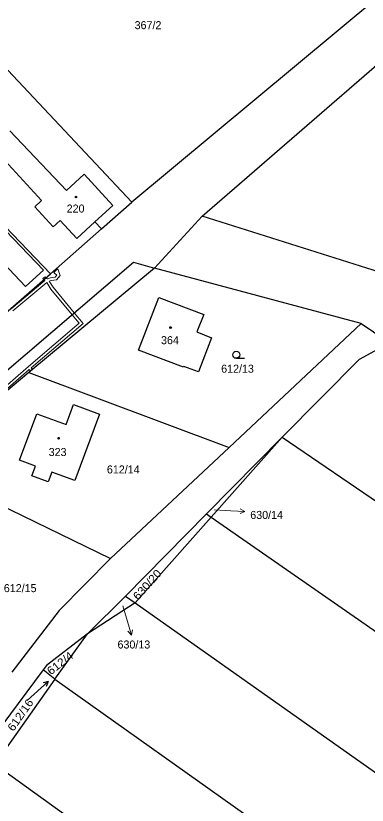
# Model space of a CAD drawing. Extents: x -694609 to -690140, y -1033292 to -1029794.
# Drawn here: x -692178.9 to -692104.2, y -1031453.2 to -1031285.6 of the extents above; entities that cross this region are included whole.
import ezdxf
from ezdxf.enums import TextEntityAlignment as Align

# ---------------------------------------------------------------- set-up
doc = ezdxf.new("R2010")
doc.units = 0
doc.header["$LTSCALE"] = 0.68
for name, color, linetype, lineweight in [('1', 7, 'Continuous', 25), ('13', 7, 'Continuous', 13), ('3', 7, 'Continuous', 25), ('4', 7, 'Continuous', 13), ('5', 7, 'Continuous', 25), ('7', 7, 'Continuous', 13)]:
    doc.layers.add(name, color=color, linetype=linetype, lineweight=lineweight)
doc.layers.add('2', color=7, linetype='Continuous')

msp = doc.modelspace()

# ---------------------------------------------------------------- linework, layer by layer
at = {"layer": '1'}
for p, q in [((-692095, -1031275.84), (-692154.22, -1031325.12)), ((-692154.22, -1031325.12), (-692192.55, -1031284.45)), ((-692180.14, -1031310.03), (-692168.15, -1031322.67)), ((-692171.54, -1031340.38), (-692191.25, -1031319.84)), ((-692168.15, -1031322.67), (-692164.4, -1031319.21)), ((-692164.4, -1031319.21), (-692158.3, -1031325.83)), ((-692160.71, -1031330.83), (-692154.22, -1031325.12)), ((-692162.09, -1031329.32), (-692158.3, -1031325.83)), ((-692139.33, -1031328.14), (-692149.46, -1031339.18)), ((-692093.23, -1031342.69), (-692139.33, -1031328.14)), ((-692162.09, -1031329.32), (-692160.71, -1031330.83)), ((-692171.54, -1031340.38), (-692160.71, -1031330.83)), ((-692201.58, -1031378.66), (-692153.91, -1031337.92)), ((-692153.91, -1031337.92), (-692149.46, -1031339.18)), ((-692181.69, -1031349.22), (-692171.54, -1031340.38)), ((-692149.46, -1031339.18), (-692176.11, -1031361.31)), ((-692105.52, -1031350.95), (-692149.46, -1031339.18)), ((-692152.84, -1031356.62), (-692148.5, -1031345.4)), ((-692148.5, -1031345.4), (-692138.94, -1031348.98)), ((-692138.94, -1031348.98), (-692140.46, -1031352.72)), ((-692133.54, -1031377.26), (-692105.52, -1031350.95)), ((-692105.52, -1031350.95), (-692099.53, -1031354.99)), ((-692140.46, -1031352.72), (-692137.3, -1031353.97)), ((-692137.3, -1031353.97), (-692140.1, -1031361.21)), ((-692105.9, -1031358.49), (-692099.53, -1031354.99)), ((-692143.28, -1031360.18), (-692152.84, -1031356.62)), ((-692122.28, -1031375.04), (-692105.9, -1031358.49)), ((-692143.23, -1031360.05), (-692143.28, -1031360.18)), ((-692140.1, -1031361.21), (-692143.23, -1031360.05)), ((-692176.11, -1031361.31), (-692199.58, -1031381)), ((-692168.18, -1031372.38), (-692166.62, -1031368.16)), ((-692166.62, -1031368.16), (-692161.14, -1031370.18)), ((-692178.09, -1031379.96), (-692174.46, -1031370.14)), ((-692174.46, -1031370.14), (-692168.18, -1031372.38)), ((-692161.14, -1031370.18), (-692166.36, -1031384.3)), ((-692138.41, -1031391.33), (-692122.28, -1031375.04)), ((-692122.28, -1031375.04), (-692137.36, -1031392.06)), ((-692122.28, -1031375.04), (-691866.47, -1031549.82)), ((-692174.69, -1031381.21), (-692178.09, -1031379.96)), ((-692199.58, -1031381), (-692158.81, -1031400.86)), ((-692175.46, -1031383.28), (-692174.69, -1031381.21)), ((-692172.02, -1031384.55), (-692175.46, -1031383.28)), ((-692171.25, -1031382.49), (-692172.02, -1031384.55)), ((-692166.36, -1031384.3), (-692171.25, -1031382.49)), ((-692155.56, -1031408.82), (-692138.41, -1031391.33)), ((-692137.36, -1031392.06), (-692153.51, -1031410.27)), ((-692138.41, -1031391.33), (-692137.36, -1031392.06)), ((-692137.36, -1031392.06), (-691875.18, -1031574.34)), ((-692169.68, -1031411.9), (-692158.81, -1031400.86)), ((-692163.69, -1031416.87), (-692155.56, -1031408.82)), ((-692155.56, -1031408.82), (-692153.51, -1031410.27)), ((-692153.51, -1031410.27), (-692163.69, -1031416.87)), ((-692153.51, -1031410.27), (-691888.96, -1031597.09)), ((-692169.68, -1031411.9), (-692179.72, -1031425)), ((-692163.69, -1031416.87), (-692172.41, -1031423.54)), ((-692170.59, -1031426.47), (-692163.69, -1031416.87)), ((-692172.41, -1031423.54), (-692173.12, -1031424.5)), ((-692170.59, -1031426.47), (-692173.12, -1031424.5)), ((-692170.59, -1031426.47), (-692183.39, -1031444.54)), ((-692170.59, -1031426.47), (-691908.31, -1031612.42)), ((-692183.39, -1031444.54), (-691926.83, -1031628.02))]:
    msp.add_line(p, q, dxfattribs=at)
for points in [[(-692139.33, -1031328.14), (-692019.58, -1031224.37), (-692016.55, -1031221.58)], [(-692176.11, -1031361.31), (-692133.54, -1031377.26), (-692158.81, -1031400.86)], [(-692173.12, -1031424.5), (-692181.85, -1031436.32), (-692183.39, -1031444.54)]]:
    msp.add_lwpolyline(points, dxfattribs=at)
at = {"layer": '13'}
for points in [[(-692179.54, -1031348.26), (-692172.31, -1031342.24), (-692171.46, -1031343.6), (-692166.94, -1031349.05), (-692166.48, -1031348.66), (-692170.98, -1031343.24), (-692171.78, -1031341.95), (-692171.37, -1031341.81), (-692170.25, -1031341.66), (-692169.46, -1031340.7), (-692169.88, -1031339.52), (-692170.06, -1031339.34), (-692170.8, -1031340.1), (-692170.63, -1031340.27), (-692170.18, -1031340.64), (-692170.57, -1031341.1), (-692171.51, -1031341.23), (-692172.18, -1031341.45), (-692172.5, -1031341.21), (-692172.95, -1031341.61), (-692172.71, -1031341.79), (-692179.9, -1031347.82)], [(-692188.05, -1031371.12), (-692176.07, -1031360.71), (-692175.79, -1031361.04), (-692175.33, -1031360.66), (-692175.61, -1031360.32), (-692164.59, -1031350.95), (-692166.48, -1031348.66), (-692166.94, -1031349.05), (-692165.43, -1031350.87), (-692176.23, -1031360.05), (-692188.43, -1031370.66)]]:
    msp.add_lwpolyline(points, dxfattribs=at)
msp.add_lwpolyline([(-692173.15, -1031341.38), (-692172.95, -1031341.61), (-692172.5, -1031341.21), (-692172.69, -1031340.99)], close=True, dxfattribs=at)
at = {"layer": '3'}
for p, q in [((-692132.053, -1031358.32), (-692130.303, -1031358.32)), ((-692172.042, -1031426.968), (-692172.433, -1031427.994))]:
    msp.add_line(p, q, dxfattribs=at)
msp.add_lwpolyline([(-692176.501, -1031430.982), (-692172.042, -1031426.968), (-692173.104, -1031427.249)], dxfattribs=at)
msp.add_circle((-692132.0529, -1031357.5698), 0.75, dxfattribs=at)
at = {"layer": '4'}
for p, q in [((-692181.23, -1031316.33), (-692173.41, -1031324.79)), ((-692173.02, -1031339.56), (-692191.65, -1031320.22)), ((-692173.41, -1031324.79), (-692174.87, -1031326.15)), ((-692165.94, -1031332.87), (-692162.09, -1031329.32)), ((-692187.74, -1031331.66), (-692176.82, -1031343.04)), ((-692176.82, -1031343.04), (-692173.02, -1031339.56))]:
    msp.add_line(p, q, dxfattribs=at)
msp.add_lwpolyline([(-692174.87, -1031326.15), (-692170.94, -1031330.41), (-692169.47, -1031329.05), (-692165.94, -1031332.87)], dxfattribs=at)
at = {"layer": '5'}
for centre in [(-692166.0968, -1031324.0692), (-692146.0268, -1031351.7892), (-692169.7968, -1031375.2892)]:
    msp.add_circle(centre, 0.175, dxfattribs=at)
at = {"layer": '7'}
for p, q in [((-692130.223, -1031390.867), (-692131.197, -1031390.315)), ((-692154.293, -1031417.11), (-692154.107, -1031416.006))]:
    msp.add_line(p, q, dxfattribs=at)
for points in [[(-692136.74, -1031390.51), (-692133.22, -1031390.71), (-692130.223, -1031390.867), (-692131.249, -1031391.315)], [(-692156.19, -1031410.9), (-692155.17, -1031414.24), (-692154.293, -1031417.11), (-692155.064, -1031416.299)]]:
    msp.add_lwpolyline(points, dxfattribs=at)

# ---------------------------------------------------------------- texts
at = {"layer": '2'}
for s, p in [('367/2', (-692150.81, -1031288.405)), ('220', (-692166.199, -1031327.355)), ('364', (-692146.149, -1031355.315)), ('612/13', (-692131.79, -1031361.375)), ('323', (-692170.019, -1031379.075)), ('612/14', (-692156.07, -1031382.775)), ('630/14', (-692125.61, -1031392.435)), ('612/15', (-692177.97, -1031407.985)), ('630/13', (-692153.81, -1031419.955))]:
    msp.add_text(s, height=1.7, dxfattribs=at).set_placement(p, align=Align.CENTER)
at = {"layer": '2', "width": 1.1}
for s, rotation, p in [('630/20', 48, (-692150.3531, -1031406.9648)), ('612/4', 38, (-692168.9813, -1031423.7455)), ('612/16', 55, (-692177.2281, -1031434.5655))]:
    msp.add_text(s, height=1.7, rotation=rotation, dxfattribs=at).set_placement(p, align=Align.CENTER)

doc.saveas('drawing.dxf')
